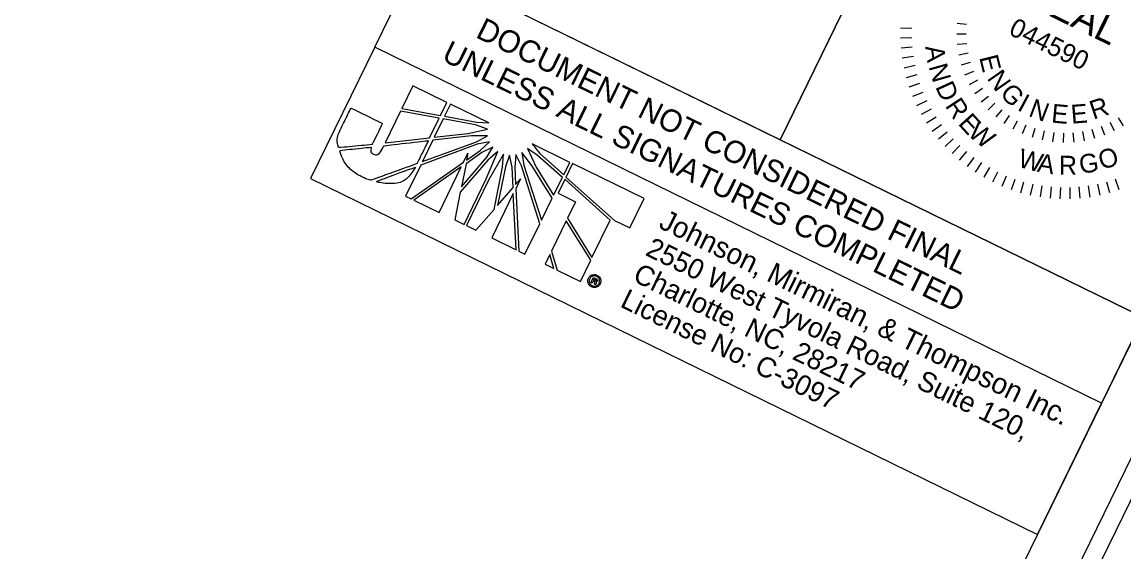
# Model space of a CAD drawing. Extents: x 1518247 to 1523638, y 635234 to 639927.
# Drawn here: x 1522074.1 to 1522346.5, y 638002.2 to 638133.1 of the extents above; entities that cross this region are included whole.
import ezdxf

# ---------------------------------------------------------------- set-up
doc = ezdxf.new("R2010")
doc.units = 0
for name, color, linetype in [('Default', 7, 'Continuous'), ('DTM TIN Hull White', 7, 'Continuous'), ('Sheet Plot Border Inside CELL', 7, 'Continuous'), ('Sheet Plot Border Outside CELL', 7, 'Continuous'), ('Sheet Sticker Exception Certification CELL', 7, 'Continuous'), ('Sheet Typical CELL', 7, 'Continuous'), ('Typical Pavement Slope CELL', 7, 'Continuous'), ('Typical Text Label CELL', 7, 'Continuous')]:
    doc.layers.add(name, color=color, linetype=linetype)

msp = doc.modelspace()

# ---------------------------------------------------------------- linework, layer by layer
at = {"layer": 'Default'}
for p, q in [((1522170.72, 638117.32), (1522168, 638111.74)), ((1522179.14, 638113.21), (1522170.72, 638117.32)), ((1522177.55, 638109.96), (1522179.14, 638113.21)), ((1522167.69, 638111.1), (1522163.86, 638103.25)), ((1522177.25, 638109.35), (1522167.69, 638111.1)), ((1522168, 638111.74), (1522177.55, 638109.96)), ((1522180.03, 638112.83), (1522178.56, 638109.81)), ((1522189.5, 638108.21), (1522180.03, 638112.83)), ((1522174.88, 638104.48), (1522177.25, 638109.35)), ((1522178.24, 638109.16), (1522176.02, 638104.61)), ((1522186.24, 638107.66), (1522178.24, 638109.16)), ((1522178.56, 638109.81), (1522186.56, 638108.32)), ((1522189.16, 638106.66), (1522186.24, 638107.66)), ((1522186.56, 638108.32), (1522189.5, 638108.21)), ((1522185.21, 638104.95), (1522175.66, 638103.87)), ((1522176.02, 638104.61), (1522184.29, 638105.52)), ((1522184.29, 638105.52), (1522189.16, 638106.66)), ((1522189.21, 638105.01), (1522185.21, 638104.95)), ((1522186.48, 638103.53), (1522189.21, 638105.01)), ((1522163.86, 638103.25), (1522174.88, 638104.48)), ((1522186.61, 638102.89), (1522172.67, 638097.74)), ((1522175.66, 638103.87), (1522173.1, 638098.62)), ((1522173.1, 638098.62), (1522186.48, 638103.53)), ((1522189.69, 638103.52), (1522186.61, 638102.89)), ((1522187.35, 638101.33), (1522189.69, 638103.52)), ((1522190.53, 638102.19), (1522187.82, 638100.86)), ((1522189.03, 638099.7), (1522190.53, 638102.19)), ((1522209.53, 638098.38), (1522200.22, 638102.98)), ((1522200.22, 638102.98), (1522202.04, 638100.72)), ((1522182.75, 638092.37), (1522189.03, 638099.7)), ((1522183.27, 638098.5), (1522184.35, 638100.72)), ((1522187.82, 638100.86), (1522183.87, 638098.08)), ((1522184.02, 638098.99), (1522187.35, 638101.33)), ((1522184.35, 638100.72), (1522184.02, 638098.99)), ((1522188.86, 638094.32), (1522191.74, 638101.13)), ((1522191.74, 638101.13), (1522189.27, 638099)), ((1522193.13, 638100.46), (1522189.46, 638094.03)), ((1522192.92, 638097.22), (1522193.13, 638100.46)), ((1522194.66, 638100.17), (1522193.62, 638097.35)), ((1522195.24, 638097.24), (1522194.66, 638100.17)), ((1522196.22, 638100.34), (1522195.93, 638097.15)), ((1522197.61, 638097.53), (1522196.22, 638100.34)), ((1522197.7, 638100.87), (1522198.19, 638097.76)), ((1522200.15, 638097.66), (1522197.7, 638100.87)), ((1522199.07, 638101.82), (1522201.19, 638097.21)), ((1522201.5, 638100.22), (1522199.07, 638101.82)), ((1522207.74, 638094.72), (1522201.5, 638100.22)), ((1522202.04, 638100.72), (1522208.05, 638095.36)), ((1522172.67, 638097.74), (1522168.94, 638090.1)), ((1522170.33, 638089.42), (1522183.27, 638098.5)), ((1522182.68, 638097.29), (1522170.98, 638089.1)), ((1522177.26, 638086.04), (1522182.68, 638097.29)), ((1522189.27, 638099), (1522182.46, 638091.07)), ((1522183.87, 638098.08), (1522182.75, 638092.37)), ((1522190.83, 638086.81), (1522192.92, 638097.22)), ((1522193.62, 638097.35), (1522191.65, 638087.79)), ((1522195.49, 638092.24), (1522195.24, 638097.24)), ((1522195.93, 638097.15), (1522196.1, 638092.92)), ((1522202.09, 638083.28), (1522197.61, 638097.53)), ((1522198.19, 638097.76), (1522202.51, 638084.15)), ((1522205.14, 638089.54), (1522200.15, 638097.66)), ((1522201.19, 638097.21), (1522205.51, 638090.29)), ((1522208.05, 638095.36), (1522209.53, 638098.38)), ((1522210.2, 638098.11), (1522208.61, 638094.86)), ((1522227.89, 638089.48), (1522210.2, 638098.11)), ((1522183.39, 638083.1), (1522188.86, 638094.32)), ((1522189.46, 638094.03), (1522183.98, 638082.81)), ((1522196.1, 638092.92), (1522197.34, 638094.38)), ((1522197.34, 638094.38), (1522196.15, 638091.92)), ((1522205.51, 638090.29), (1522207.74, 638094.72)), ((1522208.3, 638094.21), (1522206.64, 638090.82)), ((1522208.32, 638094.26), (1522208.3, 638094.21)), ((1522219.54, 638084.18), (1522208.32, 638094.26)), ((1522208.61, 638094.86), (1522208.57, 638094.76)), ((1522208.57, 638094.76), (1522220.59, 638084.07)), ((1522191.65, 638087.79), (1522195.49, 638092.24)), ((1522196.15, 638091.92), (1522196.92, 638076.45)), ((1522168.94, 638090.1), (1522170.33, 638089.42)), ((1522170.98, 638089.1), (1522177.26, 638086.04)), ((1522182.46, 638091.07), (1522181.08, 638084.23)), ((1522195.56, 638090.71), (1522190.22, 638079.77)), ((1522196.24, 638076.83), (1522195.56, 638090.71)), ((1522202.51, 638084.15), (1522205.14, 638089.54)), ((1522206.64, 638090.82), (1522210.96, 638088.71)), ((1522210.96, 638088.71), (1522208.99, 638084.67)), ((1522224.35, 638082.23), (1522227.89, 638089.48)), ((1522186.32, 638081.67), (1522190.83, 638086.81)), ((1522181.08, 638084.23), (1522183.39, 638083.1)), ((1522198.4, 638075.73), (1522202.09, 638083.28)), ((1522208.65, 638083.98), (1522204.98, 638076.45)), ((1522214.69, 638074.24), (1522208.65, 638083.98)), ((1522208.99, 638084.67), (1522215.01, 638074.89)), ((1522215.01, 638074.89), (1522219.54, 638084.18)), ((1522220.59, 638084.07), (1522224.35, 638082.23)), ((1522183.98, 638082.81), (1522186.32, 638081.67)), ((1522190.22, 638079.77), (1522196.24, 638076.83)), ((1522196.92, 638076.45), (1522198.4, 638075.73)), ((1522204.58, 638075.63), (1522203.43, 638073.27)), ((1522205.61, 638072.21), (1522204.58, 638075.63)), ((1522204.98, 638076.45), (1522206.44, 638071.8)), ((1522203.43, 638073.27), (1522205.61, 638072.21)), ((1522212.15, 638069.02), (1522214.69, 638074.24)), ((1522206.44, 638071.8), (1522212.15, 638069.02)), ((1522214.75, 638068.73), (1522215.38, 638070.02)), ((1522215.38, 638070.02), (1522215.9, 638069.76)), ((1522215.55, 638069.63), (1522215.4, 638069.33)), ((1522215.78, 638069.52), (1522215.55, 638069.63)), ((1522215.9, 638069.76), (1522215.78, 638069.52)), ((1522215.78, 638069.52), (1522215.9, 638069.76)), ((1522215.82, 638069.5), (1522215.78, 638069.52)), ((1522215.9, 638069.76), (1522215.99, 638069.72)), ((1522216.27, 638070.52), (1522216.14, 638070.25)), ((1522216.14, 638070.25), (1522216.27, 638070.52)), ((1522215.04, 638068.59), (1522214.75, 638068.73)), ((1522215.03, 638067.97), (1522214.89, 638067.69)), ((1522214.89, 638067.69), (1522215.03, 638067.97)), ((1522214.91, 638067.69), (1522214.89, 638067.69)), ((1522215.03, 638067.97), (1522215.04, 638067.97)), ((1522215.29, 638069.09), (1522215.04, 638068.59)), ((1522215.52, 638068.98), (1522215.29, 638069.09)), ((1522215.4, 638069.33), (1522215.64, 638069.21)), ((1522215.64, 638069.21), (1522215.52, 638068.98)), ((1522215.52, 638068.98), (1522215.64, 638069.21)), ((1522215.53, 638068.97), (1522215.52, 638068.98)), ((1522215.64, 638069.21), (1522215.65, 638069.21))]:
    msp.add_line(p, q, dxfattribs=at)
for points in [[(1520441.97, 637950.34), (1521954.73, 637210.48), (1522438.02, 638198.63), (1520925.25, 638938.49)], [(1522145.44, 638094.43), (1522325.13, 638006.54), (1522340.99, 638038.97), (1522161.3, 638126.86)]]:
    msp.add_lwpolyline(points, close=True, dxfattribs=at)
for points in [[(1522168, 638111.74), (1522177.55, 638109.96), (1522179.14, 638113.21), (1522170.72, 638117.32), (1522168, 638111.74)], [(1522163.86, 638103.25), (1522174.88, 638104.48), (1522177.25, 638109.35), (1522167.69, 638111.1), (1522163.86, 638103.25)], [(1522186.56, 638108.32), (1522189.5, 638108.21), (1522180.03, 638112.83), (1522178.56, 638109.81), (1522186.56, 638108.32)], [(1522178.24, 638109.16), (1522176.02, 638104.61), (1522184.29, 638105.52), (1522189.16, 638106.66), (1522186.24, 638107.66), (1522178.24, 638109.16)], [(1522175.66, 638103.87), (1522173.1, 638098.62), (1522186.48, 638103.53), (1522189.21, 638105.01), (1522185.21, 638104.95), (1522175.66, 638103.87)], [(1522189.69, 638103.52), (1522186.61, 638102.89), (1522172.67, 638097.74), (1522168.94, 638090.1), (1522170.33, 638089.42), (1522183.27, 638098.5), (1522184.35, 638100.72), (1522184.02, 638098.99), (1522187.35, 638101.33), (1522189.69, 638103.52)], [(1522190.53, 638102.19), (1522187.82, 638100.86), (1522183.87, 638098.08), (1522182.75, 638092.37), (1522189.03, 638099.7), (1522190.53, 638102.19)], [(1522202.04, 638100.72), (1522208.05, 638095.36), (1522209.53, 638098.38), (1522200.22, 638102.98), (1522202.04, 638100.72)], [(1522189.27, 638099), (1522182.46, 638091.07), (1522181.08, 638084.23), (1522183.39, 638083.1), (1522188.86, 638094.32), (1522191.74, 638101.13), (1522189.27, 638099)], [(1522193.13, 638100.46), (1522189.46, 638094.03), (1522183.98, 638082.81), (1522186.32, 638081.67), (1522190.83, 638086.81), (1522192.92, 638097.22), (1522193.13, 638100.46)], [(1522194.66, 638100.17), (1522193.62, 638097.35), (1522191.65, 638087.79), (1522195.49, 638092.24), (1522195.24, 638097.24), (1522194.66, 638100.17)], [(1522196.22, 638100.34), (1522195.93, 638097.15), (1522196.1, 638092.92), (1522197.34, 638094.38), (1522196.15, 638091.92), (1522196.92, 638076.45), (1522198.4, 638075.73), (1522202.09, 638083.28), (1522197.61, 638097.53), (1522196.22, 638100.34)], [(1522197.7, 638100.87), (1522198.19, 638097.76), (1522202.51, 638084.15), (1522205.14, 638089.54), (1522200.15, 638097.66), (1522197.7, 638100.87)], [(1522199.07, 638101.82), (1522201.19, 638097.21), (1522205.51, 638090.29), (1522207.74, 638094.72), (1522201.5, 638100.22), (1522199.07, 638101.82)], [(1522170.98, 638089.1), (1522177.26, 638086.04), (1522182.68, 638097.29), (1522170.98, 638089.1)], [(1522227.89, 638089.48), (1522210.2, 638098.11), (1522208.61, 638094.86), (1522208.57, 638094.76), (1522220.59, 638084.07), (1522224.35, 638082.23), (1522227.89, 638089.48)], [(1522208.32, 638094.26), (1522208.3, 638094.21), (1522206.64, 638090.82), (1522210.96, 638088.71), (1522208.99, 638084.67), (1522215.01, 638074.89), (1522219.54, 638084.18), (1522208.32, 638094.26)], [(1522190.22, 638079.77), (1522196.24, 638076.83), (1522195.56, 638090.71), (1522190.22, 638079.77)], [(1522208.65, 638083.98), (1522204.98, 638076.45), (1522206.44, 638071.8), (1522212.15, 638069.02), (1522214.69, 638074.24), (1522208.65, 638083.98), (1522208.65, 638083.98)], [(1522203.43, 638073.27), (1522203.43, 638073.27), (1522205.61, 638072.21), (1522204.58, 638075.63), (1522203.43, 638073.27)], [(1522215.99, 638068.51), (1522215.95, 638068.44), (1522215.94, 638068.38), (1522215.92, 638068.34), (1522215.88, 638068.18), (1522215.62, 638068.31)]]:
    msp.add_lwpolyline(points, dxfattribs=at)
for points, degree in [([(1522163.21, 638108.04), (1522163.21, 638108.04), (1522155.42, 638111.84), (1522155.42, 638111.84), (1522155.42, 638111.84), (1522153.04, 638106.97), (1522153.04, 638106.97), (1522153.04, 638106.97), (1522152.79, 638106.45), (1522152.79, 638106.45), (1522152.04, 638104.93), (1522151.96, 638103.48), (1522152.35, 638102.03), (1522152.35, 638102.03), (1522160.65, 638102.79), (1522160.69, 638102.89), (1522160.69, 638102.89), (1522163.21, 638108.04), (1522163.21, 638108.04)], 3), ([(1522160.99, 638100.44), (1522160.49, 638100.68), (1522160.2, 638101.17), (1522160.47, 638102.19), (1522160.47, 638102.19), (1522152.61, 638101.4), (1522152.61, 638101.4), (1522153.52, 638098.54), (1522155.92, 638095.92), (1522158.43, 638094.7), (1522159.08, 638094.38), (1522159.61, 638094.19), (1522160.37, 638093.99), (1522160.37, 638093.99), (1522171.77, 638098.12), (1522171.77, 638098.12), (1522171.77, 638098.12), (1522174.54, 638103.79), (1522174.54, 638103.79), (1522174.54, 638103.79), (1522163.52, 638102.54), (1522163.52, 638102.54), (1522162.48, 638100.42), (1522161.69, 638100.1), (1522160.99, 638100.44)], 3), ([(1522160.99, 638100.44), (1522160.49, 638100.68), (1522160.2, 638101.17), (1522160.47, 638102.19), (1522160.47, 638102.19), (1522152.61, 638101.4), (1522152.61, 638101.4), (1522153.52, 638098.54), (1522155.92, 638095.92), (1522158.43, 638094.7), (1522159.08, 638094.38), (1522159.61, 638094.19), (1522160.37, 638093.99), (1522160.37, 638093.99), (1522171.77, 638098.12), (1522171.77, 638098.12), (1522171.77, 638098.12), (1522174.54, 638103.79), (1522174.54, 638103.79), (1522174.54, 638103.79), (1522163.52, 638102.54), (1522163.52, 638102.54), (1522162.48, 638100.42), (1522161.69, 638100.1), (1522160.99, 638100.44)], 3), ([(1522171.34, 638097.23), (1522171.34, 638097.23), (1522161.49, 638093.67), (1522161.49, 638093.67), (1522165.08, 638092.89), (1522169.31, 638093.46), (1522171.34, 638097.23)], 3), ([(1522214.89, 638067.69), (1522214.51, 638067.88), (1522214.24, 638068.19), (1522214.09, 638068.6), (1522213.94, 638069.01), (1522213.97, 638069.42), (1522214.16, 638069.82), (1522214.36, 638070.21), (1522214.66, 638070.48), (1522215.07, 638070.6), (1522215.48, 638070.74), (1522215.88, 638070.72), (1522216.27, 638070.52)], 3), ([(1522216.14, 638070.25), (1522215.83, 638070.41), (1522215.51, 638070.43), (1522215.18, 638070.33), (1522214.85, 638070.22), (1522214.6, 638069.99), (1522214.44, 638069.68), (1522214.29, 638069.36), (1522214.27, 638069.03), (1522214.38, 638068.69), (1522214.5, 638068.36), (1522214.72, 638068.13), (1522215.03, 638067.97)], 3), ([(1522215.04, 638067.97), (1522215.36, 638067.81), (1522215.68, 638067.79), (1522216.01, 638067.9), (1522216.34, 638068.02), (1522216.59, 638068.24), (1522216.75, 638068.56), (1522216.9, 638068.87), (1522216.92, 638069.21), (1522216.81, 638069.54), (1522216.69, 638069.86), (1522216.47, 638070.09), (1522216.14, 638070.25)], 3), ([(1522215.65, 638069.21), (1522215.83, 638069.12), (1522215.96, 638069.13), (1522216.01, 638069.23), (1522216.05, 638069.33), (1522215.99, 638069.41), (1522215.82, 638069.5)], 3), ([(1522215.99, 638069.72), (1522216.31, 638069.56), (1522216.41, 638069.35), (1522216.29, 638069.1), (1522216.23, 638068.98), (1522216.14, 638068.91), (1522216, 638068.89)], 3), ([(1522216.27, 638070.52), (1522216.67, 638070.33), (1522216.94, 638070.02), (1522217.09, 638069.62), (1522217.25, 638069.22), (1522217.22, 638068.82), (1522217.03, 638068.42)], 3), ([(1522217.03, 638068.42), (1522216.83, 638068.02), (1522216.53, 638067.75), (1522216.12, 638067.6), (1522215.71, 638067.47), (1522215.3, 638067.49), (1522214.91, 638067.69)], 3), ([(1522215.73, 638068.82), (1522215.71, 638068.86), (1522215.65, 638068.92), (1522215.53, 638068.97)], 2), ([(1522215.62, 638068.31), (1522215.61, 638068.4), (1522215.63, 638068.48), (1522215.67, 638068.57), (1522215.73, 638068.69), (1522215.75, 638068.77), (1522215.73, 638068.82)], 3), ([(1522216, 638068.89), (1522216.06, 638068.8), (1522216.05, 638068.68), (1522215.99, 638068.51)], 2)]:
    msp.add_open_spline(points, degree=degree, dxfattribs=at)
at = {"layer": 'DTM TIN Hull White'}
for p, q in [((1522305.31, 638132.79), (1522307.62, 638132.57)), ((1522291.29, 638131.62), (1522294.07, 638131.53)), ((1522305.2, 638130.19), (1522307.52, 638130.2)), ((1522291.28, 638129.16), (1522294.06, 638129.23)), ((1522291.42, 638126.69), (1522294.19, 638126.94)), ((1522305.33, 638127.59), (1522307.64, 638127.82)), ((1522291.71, 638124.24), (1522294.46, 638124.65)), ((1522305.71, 638125.01), (1522307.99, 638125.47)), ((1522292.15, 638121.81), (1522294.87, 638122.39)), ((1522306.35, 638122.49), (1522308.57, 638123.16)), ((1522292.73, 638119.41), (1522295.42, 638120.15)), ((1522307.22, 638120.04), (1522309.37, 638120.92)), ((1522308.33, 638117.68), (1522310.38, 638118.77)), ((1522293.46, 638117.05), (1522296.1, 638117.95)), ((1522294.33, 638114.74), (1522296.91, 638115.8)), ((1522309.65, 638115.44), (1522311.59, 638116.72)), ((1522295.34, 638112.48), (1522297.85, 638113.7)), ((1522311.19, 638113.34), (1522313, 638114.8)), ((1522296.48, 638110.3), (1522298.91, 638111.66)), ((1522312.92, 638111.4), (1522314.58, 638113.03)), ((1522316.31, 638111.42), (1522314.82, 638109.64)), ((1522297.75, 638108.18), (1522300.1, 638109.68)), ((1522299.15, 638106.14), (1522301.4, 638107.79)), ((1522316.91, 638108.06), (1522318.22, 638109.97)), ((1522319.12, 638106.69), (1522320.24, 638108.72)), ((1522321.46, 638105.54), (1522322.38, 638107.68)), ((1522344.16, 638106.17), (1522343.12, 638108.25)), ((1522346.43, 638107.44), (1522345.2, 638109.41)), ((1522300.67, 638104.2), (1522302.81, 638105.97)), ((1522323.9, 638104.63), (1522324.61, 638106.84)), ((1522326.41, 638103.96), (1522326.9, 638106.23)), ((1522328.98, 638103.53), (1522329.25, 638105.83)), ((1522331.58, 638103.35), (1522331.63, 638105.67)), ((1522334.18, 638103.42), (1522334, 638105.74)), ((1522336.76, 638103.74), (1522336.36, 638106.03)), ((1522339.3, 638104.31), (1522338.68, 638106.55)), ((1522341.77, 638105.12), (1522340.94, 638107.29)), ((1522302.3, 638102.34), (1522304.34, 638104.25)), ((1522304.04, 638100.59), (1522305.95, 638102.62)), ((1522305.89, 638098.95), (1522307.67, 638101.09)), ((1522307.82, 638097.42), (1522309.48, 638099.66)), ((1522309.85, 638096.02), (1522311.37, 638098.35)), ((1522311.96, 638094.73), (1522313.33, 638097.15)), ((1522314.14, 638093.58), (1522315.37, 638096.08)), ((1522316.39, 638092.56), (1522317.47, 638095.13)), ((1522318.7, 638091.68), (1522319.62, 638094.31)), ((1522345.37, 638091.61), (1522344.47, 638094.24)), ((1522321.05, 638090.93), (1522321.81, 638093.61)), ((1522323.45, 638090.34), (1522324.04, 638093.06)), ((1522325.88, 638089.88), (1522326.31, 638092.64)), ((1522328.33, 638089.58), (1522328.59, 638092.36)), ((1522330.79, 638089.43), (1522330.89, 638092.21)), ((1522333.26, 638089.42), (1522333.19, 638092.21)), ((1522335.73, 638089.56), (1522335.48, 638092.34)), ((1522338.18, 638089.85), (1522337.77, 638092.61)), ((1522340.61, 638090.29), (1522340.03, 638093.02)), ((1522343.01, 638090.88), (1522342.27, 638093.56))]:
    msp.add_line(p, q, dxfattribs=at)
at = {"layer": 'Sheet Plot Border Inside CELL'}
msp.add_lwpolyline([(1522424.11, 638180.44), (1520927.06, 638912.61), (1520463.51, 637964.8), (1521960.55, 637232.62)], close=True, dxfattribs=at)
at = {"layer": 'Sheet Plot Border Outside CELL'}
msp.add_lwpolyline([(1522438.02, 638198.63), (1520925.25, 638938.49), (1520441.97, 637950.34), (1521954.73, 637210.48)], close=True, dxfattribs=at)
at = {"layer": 'Sheet Sticker Exception Certification CELL'}
for p, q in [((1522161.3, 638126.86), (1522171.62, 638147.97)), ((1522171.62, 638147.97), (1522351.32, 638060.08)), ((1522340.99, 638038.97), (1522161.3, 638126.86)), ((1522351.31, 638060.07), (1522340.99, 638038.96))]:
    msp.add_line(p, q, dxfattribs=at)
at = {"layer": 'Sheet Typical CELL'}
msp.add_line((1522310.92, 638205.07), (1522261.52, 638104.06), dxfattribs=at)
for points in [[(1522411.76, 638183.64), (1521064.29, 638842.66), (1520602.97, 637899.43), (1521950.45, 637240.41)], [(1522221.05, 638249.03), (1522310.92, 638205.07), (1522261.5, 638104.01), (1522171.62, 638147.97)], [(1522310.92, 638205.07), (1522400.76, 638161.14), (1522351.33, 638060.08), (1522261.5, 638104.01)]]:
    msp.add_lwpolyline(points, close=True, dxfattribs=at)

# ---------------------------------------------------------------- texts
at = {"layer": 'Default'}
for s, height, p in [('Johnson, Mirmiran, & Thompson Inc.', 5.1112, (1522231.24, 638082.36)), ('2550 West Tyvola Road, Suite 120,', 4.9652, (1522227.94, 638075.62)), ('Charlotte, NC, 28217', 4.9652, (1522224.82, 638069.25)), ('License No: C-3097', 4.9652, (1522221.71, 638062.88))]:
    msp.add_text(s, height=height, rotation=333.9377, dxfattribs=at).set_placement(p)
at = {"layer": 'DTM TIN Hull White'}
for s, height, rotation, p in [('SEAL', 6.965, 333.8847, (1522321.85, 638137.65)), ('044590', 4.64, 333.8847, (1522317.77, 638130.14)), ('A', 4.64, 277.8197, (1522297.38, 638127.02)), ('E', 4.64, 283.9548, (1522310.72, 638124.37)), ('N', 4.64, 285.8915, (1522298.2, 638122.1)), ('N', 4.64, 304.8099, (1522312.52, 638119.18)), ('D', 4.64, 294.5343, (1522299.82, 638117.1)), ('G', 4.64, 313.5761, (1522315.64, 638115.23)), ('R', 4.64, 303.2069, (1522302.17, 638112.38)), ('I', 4.64, 331.6709, (1522319.94, 638111.46)), ('N', 4.64, 339.3006, (1522322.7, 638109.94)), ('R', 4.64, 18.4496, (1522338.97, 638108.92)), ('E', 4.64, 312.1794, (1522305.35, 638107.91)), ('E', 4.64, 354.6926, (1522328.44, 638108.28)), ('E', 4.64, 4.6785, (1522333.58, 638107.96)), ('W', 4.64, 321.0521, (1522307.67, 638105.21)), ('W', 4.64, 345.1793, (1522320.06, 638097.4)), ('A', 4.64, 350.5013, (1522324.9, 638096.13)), ('R', 4.64, 359.5039, (1522330.41, 638095.42)), ('G', 4.64, 8.3265, (1522335.78, 638095.57)), ('O', 4.64, 17.2091, (1522341.02, 638096.53))]:
    msp.add_text(s, height=height, rotation=rotation, dxfattribs=at).set_placement(p)
at = {"layer": 'Sheet Sticker Exception Certification CELL'}
for s, p in [('DOCUMENT NOT CONSIDERED FINAL', (1522186, 638129.42)), ('UNLESS ALL SIGNATURES COMPLETED', (1522177.58, 638123.74))]:
    msp.add_text(s, height=5.5, rotation=333.9377, dxfattribs=at).set_placement(p)
at = {"layer": 'Typical Pavement Slope CELL'}
for s, p in [('-L- STA. 18+00.00 to -L- STA. 19+75.44 (BEG. BRIDGE)', (1521849.83, 638045.79)), ('-L- STA. 21+50.94 (END BRIDGE) to -L- STA. 23+50.00', (1521841.84, 638030.18))]:
    msp.add_text(s, height=11.8983, rotation=333.8962, dxfattribs=at).set_placement(p)
at = {"layer": 'Typical Text Label CELL'}
msp.add_text('USE TYPICAL SECTION NO. 2', height=11.8983, rotation=333.8962, dxfattribs=at).set_placement((1521918.44, 638041.39))

doc.saveas('drawing.dxf')
